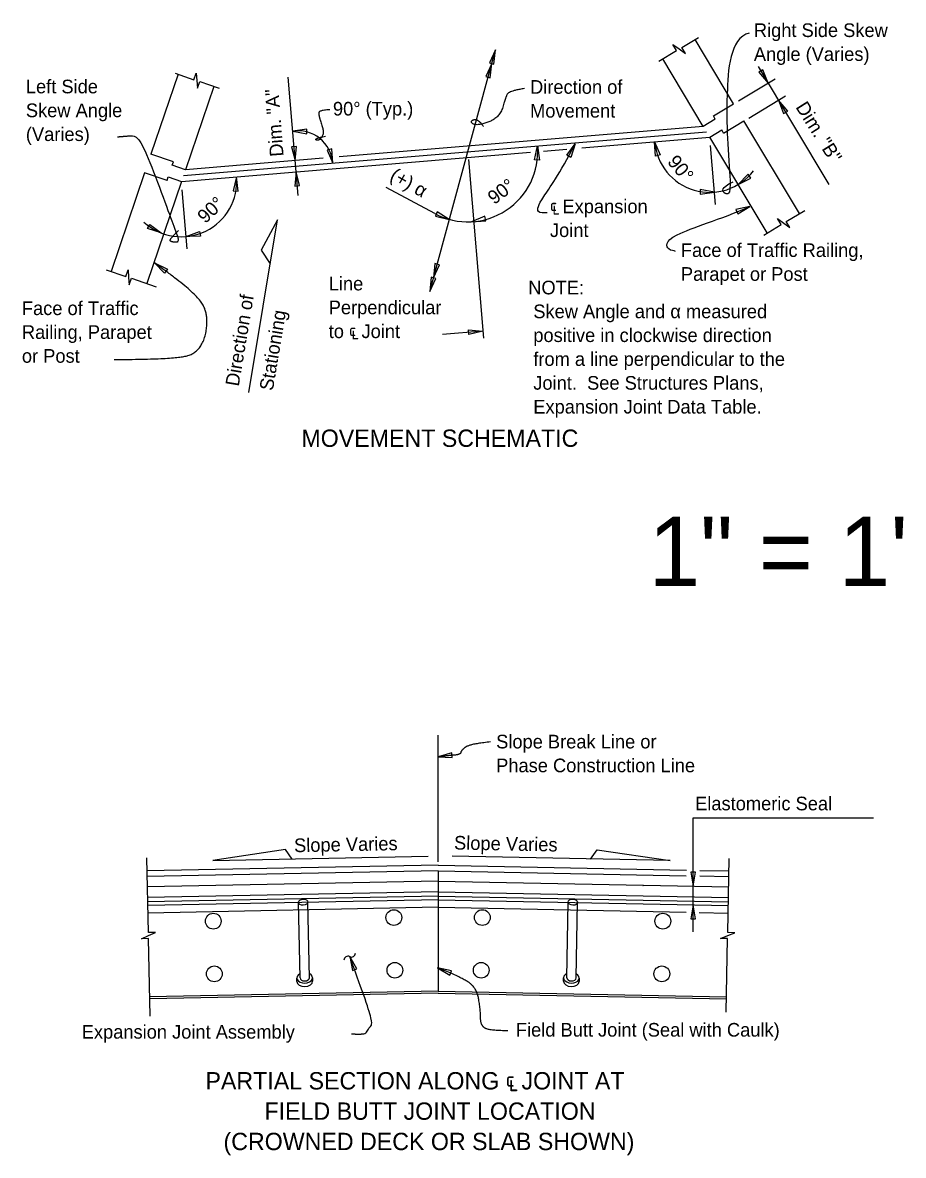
# Model space of a CAD drawing. Extents: x 0 to 26, y -2.5 to 15.3.
# Drawn here: x 10.34 to 15.22, y 7.55 to 13.82 of the extents above; entities that cross this region are included whole.
import ezdxf

# ---------------------------------------------------------------- set-up
doc = ezdxf.new("R2010")
doc.units = 0
for name, color, linetype in [('Dimension', 7, 'Continuous'), ('Miscellaneous', 7, 'Continuous'), ('SteelGirder', 7, 'Continuous'), ('SteelGirder_h', 7, 'Continuous'), ('SupstrConc', 7, 'Continuous'), ('TextStructures', 7, 'Continuous')]:
    doc.layers.add(name, color=color, linetype=linetype)

msp = doc.modelspace()

# ---------------------------------------------------------------- linework, layer by layer
at = {"layer": 'Dimension'}
for p, q in [((12.5948, 12.3344), (12.9583, 13.6718)), ((14.413, 13.58), (14.8051, 12.9265)), ((11.8658, 12.8659), (11.8109, 13.5204)), ((14.3047, 13.3899), (14.5082, 13.5121)), ((14.3618, 13.2947), (14.5653, 13.4169)), ((14.1766, 12.8157), (14.1492, 13.1418)), ((12.8087, 13.0644), (12.8917, 12.0754)), ((11.2516, 12.5703), (11.2242, 12.8963)), ((12.6228, 12.7654), (12.3529, 12.9091)), ((12.8883, 12.115), (12.6657, 12.0963)), ((12.6409, 9.1752), (12.6409, 9.8765)), ((14.054, 9.4188), (15.0526, 9.4188)), ((14.054, 9.0403), (14.054, 9.4188)), ((14.054, 8.9374), (14.054, 9.0403)), ((14.054, 8.7887), (14.054, 8.9374))]:
    msp.add_line(p, q, dxfattribs=at)
for points in [[(13.8638, 13.6099), (13.9617, 13.6687), (13.9417, 13.7019), (13.9761, 13.6774), (14.0105, 13.6528), (13.9906, 13.6861), (14.0827, 13.7414)], [(11.1846, 13.5426), (11.2895, 13.507), (11.302, 13.5437), (11.3054, 13.5016), (11.309, 13.4594), (11.3214, 13.4962), (11.429, 13.4596)], [(14.4438, 12.6464), (14.5403, 12.7044), (14.5203, 12.7376), (14.5547, 12.7131), (14.5891, 12.6885), (14.5692, 12.7217), (14.6711, 12.7829)], [(11.5928, 11.7756), (11.7521, 12.7309), (11.6614, 12.5628), (11.7116, 12.4879)], [(10.8027, 12.4549), (10.9118, 12.4178), (10.9243, 12.4545), (10.9277, 12.4124), (10.9312, 12.3703), (10.9437, 12.407), (11.0808, 12.3604)], [(11.8333, 9.1913), (11.7967, 9.2437), (11.3933, 9.1838), (12.587, 9.2077)], [(13.4852, 9.1906), (13.5218, 9.243), (13.9252, 9.1831), (12.7183, 9.2072)], [(11.0463, 8.3209), (11.0376, 8.7503), (10.9989, 8.7495), (11.0372, 8.7671), (11.0757, 8.7847), (11.0369, 8.784), (11.0286, 9.1983)], [(14.236, 8.3432), (14.2442, 8.7503), (14.2055, 8.751), (14.2446, 8.7671), (14.2836, 8.7832), (14.2449, 8.784), (14.2531, 9.1943)]]:
    msp.add_lwpolyline(points, dxfattribs=at)
for points in [[(12.9583, 13.6718), (12.925, 13.5999), (12.9506, 13.593)], [(12.9378, 13.5965), (12.9046, 13.5246), (12.9301, 13.5176)], [(14.4682, 13.488), (14.4393, 13.5618), (14.4166, 13.5482)], [(14.5253, 13.3928), (14.5541, 13.3191), (14.5768, 13.3327)], [(11.8359, 13.2224), (11.9135, 13.2064), (11.9144, 13.2328)], [(11.8496, 13.0589), (11.8563, 13.1379), (11.8299, 13.1357)], [(12.0589, 13.0444), (12.0519, 13.1233), (12.0263, 13.1166)], [(13.1757, 13.0627), (13.1916, 13.1403), (13.2022, 13.0618)], [(13.353, 13.0886), (13.4, 13.1524), (13.3766, 13.0767)], [(13.845, 13.0844), (13.8401, 13.1635), (13.8708, 13.0905)], [(11.8548, 12.9969), (11.8482, 12.9179), (11.8745, 12.9202)], [(11.5337, 12.8905), (11.5254, 12.9693), (11.5073, 12.8921)], [(14.3028, 12.9265), (14.3735, 12.9623), (14.3578, 12.9836)], [(14.1709, 12.8839), (14.093, 12.8986), (14.0925, 12.8722)], [(14.3673, 12.8056), (14.29, 12.7881), (14.3001, 12.7636)], [(12.7033, 12.7335), (12.6358, 12.7751), (12.6259, 12.7506)], [(12.8262, 12.7205), (12.9052, 12.726), (12.899, 12.7517)], [(11.1086, 12.6585), (11.033, 12.682), (11.0449, 12.7056)], [(11.2458, 12.6385), (11.3201, 12.6659), (11.325, 12.6399)], [(11.1269, 12.4364), (11.0704, 12.4919), (11.142, 12.4581)], [(12.6153, 12.4098), (12.6485, 12.4817), (12.623, 12.4886)], [(12.5948, 12.3344), (12.628, 12.4063), (12.6025, 12.4132)], [(12.8094, 12.1216), (12.8883, 12.115), (12.8116, 12.0953)], [(12.6408, 9.7572), (12.7199, 9.7534), (12.7167, 9.7797)], [(14.054, 9.0403), (14.0672, 9.1184), (14.0407, 9.1184)], [(14.054, 8.9373), (14.0408, 8.8593), (14.0672, 8.8593)], [(12.1515, 8.6507), (12.1667, 8.573), (12.1914, 8.5823)], [(12.6384, 8.5894), (12.7058, 8.5478), (12.7157, 8.5723)]]:
    msp.add_lwpolyline(points, close=True, dxfattribs=at)
for centre, radius, start, end in [((11.864, 13.0289), 0.1956, 4.55487, 98.25152), ((12.805, 13.1078), 0.3879, 241.97336, 4.7968), ((14.1453, 13.1891), 0.3062, 184.7968, 322.32194), ((11.2202, 12.9436), 0.3062, 227.27166, 4.7968), ((12.1607, 8.6709), 0.0224, 244.86266, 356.58988), ((12.1418, 8.6304), 0.0224, 64.86266, 176.58988)]:
    msp.add_arc(centre, radius, start, end, dxfattribs=at)
for points, degree in [([(14.3641, 13.7652), (14.2552, 13.7381), (14.236, 13.3739), (14.2421, 13.1617), (14.2652, 12.886), (14.2448, 12.8736), (14.2264, 12.872), (14.2038, 12.9092), (14.2743, 12.9414)], 3), ([(13.1186, 13.458), (13.036, 13.4445), (13.0154, 13.4123), (12.9926, 13.3263), (12.9434, 13.2781), (12.854, 13.2531), (12.8211, 13.2686), (12.8343, 13.2889), (12.87, 13.281), (12.8919, 13.2479)], 2), ([(12.042, 13.3406), (11.9844, 13.3376), (11.9778, 13.3135), (12.0102, 13.218), (11.9971, 13.1861), (11.9836, 13.1725), (11.9646, 13.1709), (11.9637, 13.1825), (12.0184, 13.1946)], 2), ([(10.8667, 13.1907), (10.919, 13.195), (10.9907, 13.2011), (11.185, 12.6768), (11.2083, 12.608), (11.1763, 12.6054), (11.146, 12.6184), (11.203, 12.671)], 2), ([(13.2442, 12.7693), (13.2289, 12.7693), (13.1806, 12.7649), (13.2017, 12.8349), (13.3125, 12.9791), (13.4, 13.1524)], 3), ([(13.9555, 12.5559), (13.9453, 12.5629), (13.919, 12.5531), (13.8765, 12.6397), (14.2044, 12.7329), (14.3673, 12.8056)], 3), ([(10.8478, 11.9578), (11.1562, 11.9578), (11.3247, 11.9927), (11.3756, 12.1803), (11.312, 12.3234), (11.0704, 12.4919)], 2), ([(12.9305, 9.8394), (12.8189, 9.8287), (12.7675, 9.7927), (12.7658, 9.769), (12.6904, 9.7631), (12.6409, 9.7571)], 2), ([(12.162, 8.2229), (12.2065, 8.2209), (12.2428, 8.2249), (12.259, 8.2573), (12.2882, 8.2886), (12.1515, 8.6508)], 2), ([(13.027, 8.2401), (12.9249, 8.2401), (12.8766, 8.2688), (12.8766, 8.3476), (12.8569, 8.473), (12.7799, 8.5321), (12.6385, 8.5894)], 2)]:
    msp.add_open_spline(points, degree=degree, dxfattribs=at)
at = {"layer": 'Miscellaneous'}
for p, q in [((11.2311, 12.9758), (14.1274, 13.2188)), ((13.7754, 9.0437), (13.7758, 9.0444))]:
    msp.add_line(p, q, dxfattribs=at)
for points in [[(12.6409, 9.0685), (11.0313, 9.0363)], [(12.6409, 9.0685), (14.2506, 9.0363)], [(12.6426, 8.986), (11.0329, 8.9538)], [(12.6409, 8.986), (14.2489, 8.9538)], [(12.643, 8.9657), (11.0333, 8.9335)], [(12.6409, 8.9656), (14.2485, 8.9335)]]:
    msp.add_lwpolyline(points, dxfattribs=at)
at = {"layer": 'SteelGirder'}
for p, q in [((11.2421, 13.008), (11.169, 13.0328)), ((12.6409, 9.1262), (12.6409, 9.0685)), ((12.6409, 8.9656), (12.6409, 8.4594))]:
    msp.add_line(p, q, dxfattribs=at)
for points in [[(14.1095, 13.2486), (12.094, 13.0795)], [(14.1758, 13.2883), (14.1095, 13.2486)], [(13.4364, 13.1296), (14.1453, 13.1891), (14.2115, 13.2288)], [(13.2253, 13.1119), (13.3546, 13.1228)], [(11.1471, 12.9684), (11.2202, 12.9436), (13.152, 13.1057)], [(12.0055, 13.0721), (11.2421, 13.008)], [(12.6409, 9.1262), (11.0301, 9.094)], [(12.6409, 9.1262), (14.015, 9.0987)], [(14.0895, 9.0973), (14.2517, 9.094)], [(12.6409, 8.4594), (11.0435, 8.4274)], [(12.6409, 8.4594), (14.2384, 8.4274)]]:
    msp.add_lwpolyline(points, dxfattribs=at)
at = {"layer": 'SteelGirder_h'}
for p, q in [((12.6409, 9.0685), (12.6409, 8.9656)), ((11.8766, 8.5324), (11.8682, 8.9516)), ((11.9287, 8.5335), (11.9203, 8.9527)), ((13.3532, 8.5335), (13.3616, 8.9527)), ((13.4053, 8.5324), (13.4136, 8.9516)), ((11.8595, 8.5124), (11.8591, 8.5321)), ((11.9462, 8.5338), (11.9466, 8.5141)), ((13.3352, 8.5141), (13.3356, 8.5338)), ((13.4228, 8.5321), (13.4224, 8.5124))]:
    msp.add_line(p, q, dxfattribs=at)
for points in [[(12.6409, 9.0102), (11.0324, 8.978)], [(12.6409, 9.0102), (14.2494, 8.978)], [(12.6409, 8.9239), (11.0342, 8.8918)], [(12.6409, 8.9239), (14.0155, 8.8964)], [(14.0861, 8.895), (14.2477, 8.8918)]]:
    msp.add_lwpolyline(points, dxfattribs=at)
for centre in [(12.3961, 8.8669), (12.8858, 8.8669), (11.3963, 8.8469), (13.8856, 8.8469), (11.4021, 8.5552), (12.4019, 8.5752), (12.88, 8.5752), (13.8798, 8.5552)]:
    msp.add_circle(centre, 0.0436, dxfattribs=at)
for centre, major_axis in [((11.8943, 8.9521), (0.026, 0.0005)), ((13.3876, 8.9521), (0.026, -0.0005))]:
    msp.add_ellipse(centre, major_axis=major_axis, ratio=0.654774, dxfattribs=at)
for centre, major_axis, ratio, start_param, end_param in [((11.9026, 8.533), (0.0436, 0.0009), 0.654766, 2.211147, 7.21363), ((11.9026, 8.533), (0.026, 0.0005), 0.654774, 3.1416, 6.283178), ((13.3792, 8.533), (0.0436, -0.0009), 0.654766, 2.211147, 7.21363), ((13.3792, 8.533), (0.026, -0.0005), 0.654774, 3.1416, 6.283178), ((11.903, 8.5133), (0.0436, 0.0009), 0.654766, 3.141593, 6.283185), ((13.3788, 8.5133), (0.0436, -0.0009), 0.654766, 3.141593, 6.283185)]:
    msp.add_ellipse(centre, major_axis=major_axis, ratio=ratio, start_param=start_param, end_param=end_param, dxfattribs=at)
at = {"layer": 'SupstrConc'}
for p, q in [((14.2776, 13.3736), (14.0638, 13.7299)), ((14.1096, 13.2486), (13.8851, 13.6227)), ((11.2014, 13.5369), (11.0514, 13.0946)), ((11.3988, 13.4699), (11.2421, 13.008)), ((14.1651, 13.3061), (14.2776, 13.3737)), ((14.1758, 13.2883), (14.1651, 13.3061)), ((14.2222, 13.211), (14.3347, 13.2785)), ((14.6424, 12.7656), (14.3347, 13.2785)), ((14.4637, 12.6584), (14.1453, 13.1891)), ((14.2222, 13.211), (14.2115, 13.2288)), ((11.1756, 13.0525), (11.0514, 13.0946)), ((11.169, 13.0328), (11.1756, 13.0525)), ((11.0162, 12.9909), (10.8311, 12.4452)), ((11.1404, 12.9487), (11.0162, 12.9909)), ((11.2202, 12.9436), (11.0284, 12.3782)), ((11.1404, 12.9487), (11.1471, 12.9684))]:
    msp.add_line(p, q, dxfattribs=at)
for points in [[(12.6409, 9.1574), (11.0295, 9.1252)], [(12.6409, 9.1574), (14.0156, 9.1299)], [(14.0902, 9.1284), (14.2524, 9.1252)], [(12.6409, 8.449), (11.0443, 8.4171)], [(12.6409, 8.449), (14.2376, 8.4171)]]:
    msp.add_lwpolyline(points, dxfattribs=at)

# ---------------------------------------------------------------- texts
at = {"layer": 'TextStructures'}
for s, height, p in [('Right Side Skew ', 0.0756, (14.3895, 13.7432)), ('Angle (Varies)', 0.0756, (14.3895, 13.6112)), ('Left Side ', 0.0756, (10.3587, 13.4314)), ('Direction of ', 0.0756, (13.1503, 13.4291)), ('Skew Angle ', 0.0756, (10.3587, 13.2994)), ('90° (Typ.) ', 0.0756, (12.0589, 13.3085)), ('Movement', 0.0756, (13.1503, 13.2971)), ('(Varies)', 0.0756, (10.3587, 13.1674)), ('℄ Expansion ', 0.0756, (13.2605, 12.7678)), ('Joint', 0.0756, (13.2605, 12.6358)), ('Face of Traffic Railing, ', 0.0756, (13.9854, 12.5252)), ('Parapet or Post', 0.0756, (13.9854, 12.3932)), ('Line ', 0.0756, (12.0356, 12.3401)), ('NOTE:  ', 0.0756, (13.1402, 12.3182)), ('Face of Traffic', 0.0756, (10.3366, 12.2035)), ('Perpendicular ', 0.0756, (12.0356, 12.2081)), (' Skew Angle and α measured ', 0.0756, (13.1402, 12.1862)), ('Railing, Parapet', 0.0756, (10.3366, 12.0715)), ('to ℄ Joint', 0.0756, (12.0356, 12.0761)), (' positive in clockwise direction ', 0.0756, (13.1402, 12.0542)), ('or Post', 0.0756, (10.3366, 11.9395)), (' from a line perpendicular to the ', 0.0756, (13.1402, 11.9222)), (' Joint.  See Structures Plans, ', 0.0756, (13.1402, 11.7902)), (' Expansion Joint Data Table.', 0.0756, (13.1402, 11.6582)), ('MOVEMENT SCHEMATIC', 0.096, (11.8843, 11.4736)), ('1" = 1\'', 0.38396, (13.8064, 10.7023)), ('Slope Break Line or', 0.0756, (12.9626, 9.8037)), ('Phase Construction Line', 0.0756, (12.9626, 9.6717)), ('Elastomeric Seal', 0.0756, (14.0643, 9.4608)), ('Field Butt Joint (Seal with Caulk)', 0.0756, (13.0717, 8.2076)), ('Expansion Joint Assembly', 0.0756, (10.668, 8.1964)), ('PARTIAL SECTION ALONG ℄ JOINT AT', 0.096, (11.3532, 7.9151)), ('FIELD BUTT JOINT LOCATION', 0.096, (11.6799, 7.7471)), ('(CROWNED DECK OR SLAB SHOWN)', 0.096, (11.4529, 7.5791))]:
    msp.add_text(s, height=height, dxfattribs=at).set_placement(p)
for s, rotation, p in [('Dim. "A"', 94.38962, (11.786, 13.0836)), ('Dim. "B"', 302.13907, (14.6181, 13.3555)), ('90°', 309.75647, (13.9067, 13.0503)), ('(+) α', 330.50107, (12.3685, 12.9565)), ('90°', 37.17757, (12.952, 12.8124)), ('90°', 43.1571, (11.3518, 12.7068)), ('Direction of', 80.53332, (11.5372, 11.8056)), ('Stationing', 80.53332, (11.726, 11.7812)), ('Slope Varies', 1.14567, (11.8444, 9.2288)), ('Slope Varies', 358.85433, (12.7289, 9.244))]:
    msp.add_text(s, height=0.0756, rotation=rotation, dxfattribs=at).set_placement(p)

doc.saveas('drawing.dxf')
